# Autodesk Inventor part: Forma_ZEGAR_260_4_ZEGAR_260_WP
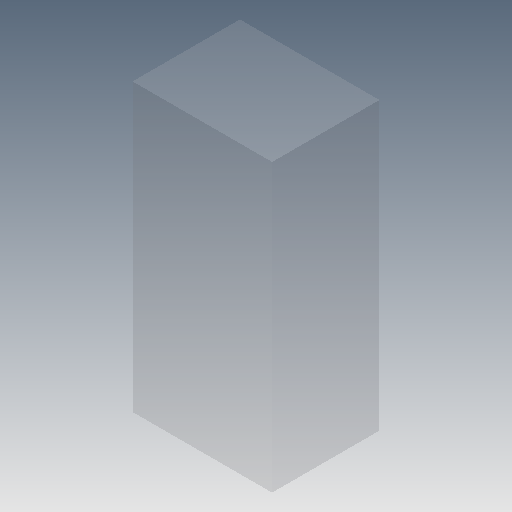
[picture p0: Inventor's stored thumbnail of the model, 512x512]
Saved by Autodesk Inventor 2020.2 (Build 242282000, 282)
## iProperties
Created: 2015-01
Part Number: Forma_ZEGAR_260_4_ZEGAR_260_WP
Material: Ogólny
Document SubType Name: Modeling
Designer: F.Stasiak
Density: 1 g/cm^3
Appearance: Domyślna
Catalog Web Link: www.expertbooks.pl
Manager: www.cadconsulting.pl
Company: Fabian Stasiak CAD Consulting
d0: -30.000 mm
d1: 39.000 mm
d2: 39.000 mm
d3: 80.000 mm
d4: 80.000 mm
d5: 60.000 mm
d6: 0.00 deg
Xmin: -39.000 mm
Ymin: -80.000 mm
Zmin: -30.000 mm
Xmax: 39.000 mm
Ymax: 80.000 mm
Zmax: 30.000 mm
Author: F.Stasiak
Subject: Zbiór ćwiczeń. Autodesk Inventor 2020. Kurs Professional
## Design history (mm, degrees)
sketch "Szkic1"
  geometry: L1 (-39, 80)-(39, 80); L2 (39, 80)-(39, -80); L3 (39, -80)-(-39, -80); L4 (-39, -80)-(-39, 80); 1 further point
  constraints: 8 end point, 2 parallel, 1 horizontal, 1 perpendicular, 1 other
  dimensions: "d1" = 39 distance from line of L4 point (0, 0) (= -Xmin); "d2" = 39 distance from line of L2 point (0, 0) (= Xmax); "d3" = 80 distance from line of L3 point (0, 0) (= -Ymin); "d4" = 80 distance from line of L1 point (0, 0) (= Ymax)
extrude "Wyciągnięcie proste1" join sketch "Szkic1" distance "d5" = 60 (= Zmax - Zmin); taper "d6" = 0 deg
node "Bryła1"
other parameters: "Xmin" = -39 [user parameter; used in 1 equation term], "Ymin" = -80 [user parameter; used in 1 equation term], "Zmin" = -30 [user parameter; used in 1 equation term], "Xmax" = 39 [user parameter; used in 1 equation term], "Ymax" = 80 [user parameter; used in 1 equation term], "Zmax" = 30 [user parameter; used in 1 equation term], "d0" = -30
